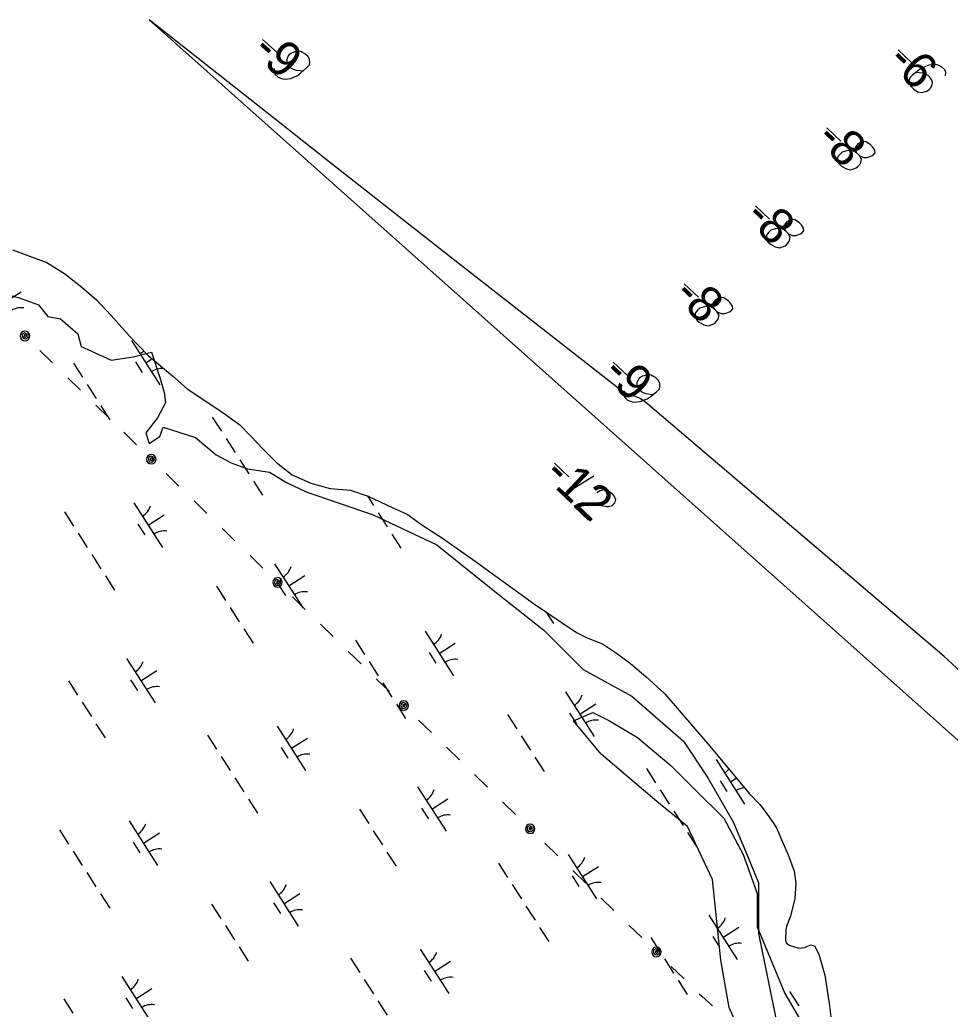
# Model space of a CAD drawing. Extents: x 3962991 to 3983549, y 181631 to 204078.
# Drawn here: x 3977393 to 3978274, y 189193 to 190129 of the extents above; entities that cross this region are included whole.
import ezdxf

# ---------------------------------------------------------------- set-up
doc = ezdxf.new("R2010")
doc.units = 0
for name, color, linetype in [('V-ANNO-MASK', 7, 'Continuous'), ('V-ANNO-MASK2', 7, 'Continuous'), ('V-RIVR-EDGE', 7, 'Continuous'), ('V-RIVR-RANG', 7, 'Continuous'), ('V-SITE-VEGE', 7, 'Continuous'), ('V-TOPO-DPTH', 7, 'Continuous'), ('V-TOPO-MINR', 7, 'Continuous'), ('V-UTIL-LINE', 7, 'Continuous'), ('V-WETL-SWMP', 7, 'Continuous')]:
    doc.layers.add(name, color=color, linetype=linetype)

msp = doc.modelspace()

# ---------------------------------------------------------------- linework, layer by layer
at = {"layer": 'V-ANNO-MASK2'}
for p, q in [((3977622.66, 190110.7), (3977636.5, 190098.47)), ((3978224.28, 190101.01), (3978237.7, 190088.33)), ((3978156.67, 190027.33), (3978170.1, 190014.65)), ((3978089.26, 189953.47), (3978102.68, 189940.79)), ((3978021.84, 189879.61), (3978035.27, 189866.93)), ((3977954.71, 189805.48), (3977968.14, 189792.8)), ((3977899.07, 189709.61), (3977912.47, 189696.9)), ((3977936.15, 189697.32), (3977906.58, 189679.2))]:
    msp.add_line(p, q, dxfattribs=at)
for points in [[(3977633.69, 190083.35), (3977633.35, 190079.78), (3977634.6, 190077.61), (3977637.37, 190075.17), (3977640.05, 190074.21), (3977641.58, 190073.56), (3977643.09, 190073.28), (3977649.4, 190074.04), (3977655.77, 190076.86), (3977658.63, 190078.9), (3977664.49, 190083.94), (3977667.11, 190086.9), (3977667.37, 190088.79), (3977667.18, 190091.76), (3977666.94, 190092.68), (3977665.49, 190095.02), (3977662.92, 190097.3), (3977660.59, 190098.65), (3977658.86, 190099.47), (3977655.49, 190099.64), (3977650.72, 190098.23), (3977648.38, 190096.77), (3977646.98, 190095.19), (3977645.7, 190091.75), (3977645.61, 190090.06), (3977646.3, 190088.05), (3977648.14, 190085.36), (3977649.92, 190083.79), (3977652.62, 190082.46), (3977654.53, 190081.83), (3977658.3, 190081.31), (3977660.36, 190081.25), (3977661.47, 190081.32)], [(3978269.02, 190076.53), (3978269.47, 190080.09), (3978268.29, 190082.3), (3978265.42, 190085.01), (3978262.77, 190086.06), (3978261.26, 190086.76), (3978259.76, 190087.09), (3978253.43, 190086.54), (3978246.97, 190083.93), (3978243.86, 190081.79), (3978237.84, 190076.95), (3978235.49, 190074.46), (3978234.81, 190072.2), (3978234.89, 190069.21), (3978235.1, 190068.29), (3978236.85, 190065.91), (3978239.15, 190063.74), (3978241.25, 190062.12), (3978242.95, 190061.23), (3978246.51, 190060.78), (3978251.33, 190062.03), (3978253.72, 190063.41), (3978255.16, 190064.94), (3978256.56, 190068.34), (3978256.7, 190070.02), (3978256.07, 190072.43), (3978254.31, 190075.18), (3978252.59, 190076.81), (3978249.93, 190078.23), (3978248.05, 190078.92), (3978244.12, 190079.37), (3978242.06, 190079.5), (3978240.94, 190079.46)], [(3978184.97, 190003.5), (3978187.65, 190000.97), (3978188.6, 190000.44), (3978191.81, 189999.22), (3978194.98, 189999.13), (3978200.34, 190000.96), (3978202.51, 190003.63), (3978202.25, 190006.05), (3978200.11, 190009.16), (3978198.19, 190010.97), (3978194, 190013.84), (3978191.38, 190014.14), (3978188.42, 190013.31), (3978186.22, 190012.12), (3978183.88, 190008.89), (3978183.56, 190007.01), (3978184.97, 190003.5), (3978181.18, 190005.64), (3978175.58, 190005.48), (3978171.33, 190004.05), (3978169.33, 190002.31), (3978166.98, 189999.45), (3978166.9, 189995.9), (3978168.48, 189992.96), (3978170.78, 189990.79), (3978175.33, 189988.3), (3978179.64, 189987.49), (3978184.63, 189989.31), (3978185.91, 189990.28), (3978188.61, 189993.53), (3978189.61, 189997.67), (3978187.65, 190000.97)], [(3978117.55, 189929.65), (3978120.24, 189927.11), (3978121.19, 189926.58), (3978124.39, 189925.36), (3978127.57, 189925.27), (3978132.93, 189927.1), (3978135.09, 189929.77), (3978134.83, 189932.19), (3978132.69, 189935.3), (3978130.78, 189937.11), (3978126.59, 189939.98), (3978123.97, 189940.28), (3978121.01, 189939.45), (3978118.8, 189938.27), (3978116.47, 189935.03), (3978116.15, 189933.15), (3978117.55, 189929.65), (3978113.76, 189931.78), (3978108.17, 189931.62), (3978103.92, 189930.19), (3978101.91, 189928.45), (3978099.57, 189925.59), (3978099.48, 189922.04), (3978101.06, 189919.1), (3978103.36, 189916.93), (3978107.91, 189914.44), (3978112.23, 189913.63), (3978117.21, 189915.46), (3978118.49, 189916.42), (3978121.2, 189919.67), (3978122.2, 189923.81), (3978120.24, 189927.11)], [(3978050.14, 189855.79), (3978052.82, 189853.25), (3978053.77, 189852.72), (3978056.98, 189851.5), (3978060.15, 189851.41), (3978065.51, 189853.24), (3978067.67, 189855.91), (3978067.42, 189858.33), (3978065.28, 189861.44), (3978063.36, 189863.25), (3978059.17, 189866.12), (3978056.55, 189866.42), (3978053.59, 189865.59), (3978051.38, 189864.41), (3978049.05, 189861.17), (3978048.73, 189859.29), (3978050.14, 189855.79), (3978046.35, 189857.92), (3978040.75, 189857.76), (3978036.5, 189856.33), (3978034.5, 189854.6), (3978032.15, 189851.73), (3978032.07, 189848.18), (3978033.64, 189845.24), (3978035.95, 189843.07), (3978040.49, 189840.58), (3978044.81, 189839.77), (3978049.8, 189841.6), (3978051.07, 189842.57), (3978053.78, 189845.81), (3978054.78, 189849.95), (3978052.82, 189853.25)], [(3977964.83, 189777.78), (3977964.38, 189774.22), (3977965.56, 189772.02), (3977968.24, 189769.48), (3977970.88, 189768.44), (3977972.4, 189767.73), (3977973.9, 189767.4), (3977980.23, 189767.96), (3977986.68, 189770.57), (3977989.61, 189772.51), (3977995.63, 189777.35), (3977998.35, 189780.23), (3977998.67, 189782.1), (3977998.59, 189785.09), (3977998.37, 189786.01), (3977997, 189788.4), (3977994.51, 189790.75), (3977992.23, 189792.18), (3977990.52, 189793.07), (3977987.16, 189793.34), (3977982.34, 189792.09), (3977979.95, 189790.71), (3977978.5, 189789.18), (3977977.11, 189785.78), (3977976.97, 189784.1), (3977977.59, 189782.06), (3977979.34, 189779.31), (3977981.07, 189777.68), (3977983.72, 189776.27), (3977985.61, 189775.57), (3977989.36, 189774.93), (3977991.42, 189774.81), (3977992.53, 189774.84)], [(3977938.98, 189681.91), (3977942.28, 189683.86), (3977945.99, 189684.71), (3977948.62, 189684.03), (3977950.89, 189682.97), (3977952.41, 189681.89), (3977953.37, 189680.98), (3977954.91, 189679.15), (3977955.69, 189677.68), (3977956.09, 189676.94), (3977956.69, 189675.28), (3977956.54, 189673.97), (3977956.19, 189672.84), (3977955.84, 189672.09), (3977955.3, 189671.14), (3977954.39, 189670.18), (3977953.3, 189669.41), (3977952.56, 189669.02), (3977951.45, 189668.61), (3977950.15, 189668.39), (3977949.03, 189668.37), (3977925.42, 189672.23), (3977921.35, 189671), (3977917.68, 189668.67), (3977931.26, 189655.78)]]:
    msp.add_lwpolyline(points, dxfattribs=at)
at = {"layer": 'V-RIVR-EDGE'}
msp.add_lwpolyline([(3977377.98, 189870.44), (3977393.27, 189866.07), (3977410.74, 189859.51), (3977419.48, 189848.59), (3977431.49, 189846.41), (3977447.88, 189832.21), (3977451.15, 189820.2), (3977460.98, 189815.83), (3977479.55, 189807.09), (3977500.3, 189810.37), (3977517.77, 189814.74), (3977525.42, 189790.71), (3977529.79, 189776.51), (3977530.88, 189766.68), (3977523.24, 189752.48), (3977512.31, 189738.29), (3977515.59, 189728.46), (3977525.42, 189735.01), (3977528.7, 189743.75), (3977559.28, 189733.92), (3977578.94, 189717.53), (3977593.13, 189709.89), (3977608.42, 189704.43), (3977629.17, 189701.15), (3977645.56, 189691.32), (3977664.12, 189682.59), (3977727.47, 189660.74), (3977787.54, 189632.35), (3977842.14, 189588.66), (3977889.11, 189551.53), (3977926.24, 189514.39), (3977972.11, 189489.27), (3978021.26, 189446.68), (3978044.19, 189411.73), (3978068.22, 189370.23), (3978082.42, 189336.37), (3978092.25, 189312.35), (3978092.25, 189264.29), (3978109.72, 189178.01)], dxfattribs=at)
at = {"layer": 'V-SITE-VEGE'}
msp.add_lwpolyline([(3978085.5, 189146.87), (3978064.43, 189194.3), (3978056.53, 189239.1), (3978048.63, 189315.52), (3978024.93, 189365.6), (3977995.95, 189389.32), (3977943.27, 189434.12), (3977916.94, 189465.74), (3977935.38, 189473.64), (3977951.18, 189465.74), (3977977.52, 189449.93), (3978009.12, 189423.57), (3978032.82, 189399.86), (3978059.16, 189373.5), (3978077.6, 189339.24), (3978090.77, 189302.35), (3978090.77, 189270.73), (3978117.11, 189207.48), (3978135.55, 189175.86)], dxfattribs=at)
at = {"layer": 'V-TOPO-DPTH'}
msp.add_lwpolyline([(3978299.23, 189497.8), (3978267.78, 189526.71), (3977985.41, 189767.28), (3977982.59, 189769.38), (3977979.62, 189771.19), (3977976.42, 189772.58), (3977973.09, 189773.69), (3977969.74, 189774.79), (3977966.51, 189776.14), (3977963.48, 189777.88), (3977960.57, 189779.87), (3977850.75, 189865.64), (3977794.76, 189909.45), (3977738.82, 189953.32), (3977682.96, 189997.29), (3977627.14, 190041.32), (3977515.59, 190129.47), (3978679.07, 189092.54)], dxfattribs=at)
at = {"layer": 'V-TOPO-MINR'}
msp.add_lwpolyline([(3978299.23, 189497.8), (3978267.78, 189526.71), (3977985.41, 189767.28), (3977982.59, 189769.38), (3977979.62, 189771.19), (3977976.42, 189772.58), (3977973.09, 189773.69), (3977969.74, 189774.79), (3977966.51, 189776.14), (3977963.48, 189777.88), (3977960.57, 189779.87), (3977850.75, 189865.64), (3977794.76, 189909.45), (3977738.82, 189953.32), (3977682.96, 189997.29), (3977627.14, 190041.32), (3977515.59, 190129.47)], dxfattribs=at)
at = {"layer": 'V-UTIL-LINE'}
for points in [[(3977397.91, 189830.12), (3977398.15, 189831.54), (3977397.1, 189831.04), (3977396.91, 189829.68), (3977398.06, 189828.78), (3977399.3, 189829.94), (3977399.33, 189832.29), (3977397.32, 189833), (3977395.22, 189831.78), (3977395.14, 189829.49), (3977396.36, 189827.62), (3977398.76, 189827.42), (3977400.8, 189829.27), (3977401.05, 189833.34), (3977399.58, 189834.3), (3977397.86, 189834.62), (3977396.14, 189834.26), (3977394.69, 189833.27), (3977393.73, 189831.79), (3977393.41, 189830.07), (3977393.78, 189828.35), (3977394.77, 189826.9), (3977396.24, 189825.94), (3977397.97, 189825.62), (3977399.68, 189825.99), (3977401.13, 189826.98), (3977402.09, 189828.45), (3977402.41, 189830.18), (3977402.05, 189831.9), (3977401.05, 189833.34)], [(3977411.92, 189816.47), (3977424.08, 189804.59)], [(3977438.4, 189790.63), (3977450.57, 189778.75)], [(3977464.88, 189764.78), (3977477.05, 189752.91)], [(3977491.36, 189738.94), (3977503.53, 189727.07)], [(3977517.43, 189713.49), (3977517.67, 189714.9), (3977516.62, 189714.41), (3977516.42, 189713.05), (3977517.58, 189712.15), (3977518.82, 189713.3), (3977518.85, 189715.65), (3977516.84, 189716.37), (3977514.74, 189715.14), (3977514.66, 189712.85), (3977515.88, 189710.98), (3977518.28, 189710.78), (3977520.32, 189712.64), (3977520.57, 189716.71), (3977519.1, 189717.66), (3977517.38, 189717.99), (3977515.66, 189717.62), (3977514.21, 189716.63), (3977513.25, 189715.16), (3977512.93, 189713.43), (3977513.29, 189711.71), (3977514.29, 189710.27), (3977515.76, 189709.31), (3977517.49, 189708.99), (3977519.2, 189709.35), (3977520.65, 189710.34), (3977521.61, 189711.81), (3977521.93, 189713.54), (3977521.57, 189715.26), (3977520.57, 189716.71)], [(3977531.44, 189699.83), (3977543.6, 189687.96)], [(3977557.92, 189673.99), (3977570.08, 189662.12)], [(3977584.4, 189648.15), (3977596.56, 189636.27)], [(3977610.88, 189622.3), (3977623.04, 189610.43)], [(3977636.95, 189596.85), (3977637.19, 189598.27), (3977636.14, 189597.77), (3977635.94, 189596.41), (3977637.1, 189595.51), (3977638.34, 189596.67), (3977638.37, 189599.01), (3977636.36, 189599.73), (3977634.26, 189598.5), (3977634.17, 189596.22), (3977635.4, 189594.35), (3977637.8, 189594.15), (3977639.84, 189596), (3977640.09, 189600.07), (3977638.62, 189601.03), (3977636.89, 189601.35), (3977635.18, 189600.99), (3977633.73, 189599.99), (3977632.77, 189598.52), (3977632.45, 189596.8), (3977632.81, 189595.08), (3977633.81, 189593.63), (3977635.28, 189592.67), (3977637, 189592.35), (3977638.72, 189592.71), (3977640.17, 189593.71), (3977641.13, 189595.18), (3977641.45, 189596.91), (3977641.09, 189598.62), (3977640.09, 189600.07)], [(3977650.96, 189583.19), (3977663.12, 189571.32)], [(3977677.44, 189557.35), (3977689.6, 189545.48)], [(3977703.92, 189531.51), (3977716.08, 189519.64)], [(3977730.4, 189505.67), (3977742.56, 189493.79)], [(3977756.47, 189480.21), (3977756.71, 189481.63), (3977755.66, 189481.13), (3977755.46, 189479.77), (3977756.62, 189478.87), (3977757.86, 189480.03), (3977757.89, 189482.38), (3977755.88, 189483.09), (3977753.78, 189481.87), (3977753.69, 189479.58), (3977754.92, 189477.71), (3977757.32, 189477.51), (3977759.36, 189479.36), (3977759.61, 189483.43), (3977758.14, 189484.39), (3977756.41, 189484.71), (3977754.7, 189484.35), (3977753.25, 189483.36), (3977752.29, 189481.88), (3977751.97, 189480.16), (3977752.33, 189478.44), (3977753.33, 189476.99), (3977754.8, 189476.04), (3977756.52, 189475.71), (3977758.24, 189476.08), (3977759.69, 189477.07), (3977760.65, 189478.54), (3977760.97, 189480.27), (3977760.61, 189481.99), (3977759.61, 189483.43)], [(3977770.47, 189466.55), (3977782.64, 189454.68)], [(3977796.95, 189440.71), (3977809.12, 189428.84)], [(3977823.43, 189414.87), (3977835.6, 189403)], [(3977849.91, 189389.03), (3977862.08, 189377.16)], [(3977875.99, 189363.58), (3977876.23, 189365), (3977875.18, 189364.5), (3977874.98, 189363.14), (3977876.14, 189362.24), (3977877.38, 189363.4), (3977877.41, 189365.74), (3977875.4, 189366.46), (3977873.3, 189365.23), (3977873.21, 189362.94), (3977874.44, 189361.07), (3977876.84, 189360.87), (3977878.88, 189362.73), (3977879.13, 189366.8), (3977877.66, 189367.76), (3977875.93, 189368.08), (3977874.22, 189367.71), (3977872.77, 189366.72), (3977871.81, 189365.25), (3977871.49, 189363.52), (3977871.85, 189361.8), (3977872.85, 189360.36), (3977874.32, 189359.4), (3977876.04, 189359.08), (3977877.76, 189359.44), (3977879.21, 189360.43), (3977880.17, 189361.91), (3977880.49, 189363.63), (3977880.13, 189365.35), (3977879.13, 189366.8)], [(3977889.99, 189349.92), (3977902.16, 189338.04)], [(3977916.47, 189324.07), (3977928.64, 189312.2)], [(3977942.95, 189298.23), (3977955.12, 189286.36)], [(3977969.43, 189272.39), (3977981.6, 189260.52)], [(3977995.51, 189246.94), (3977995.75, 189248.36), (3977994.7, 189247.86), (3977994.5, 189246.5), (3977995.66, 189245.6), (3977996.9, 189246.76), (3977996.93, 189249.1), (3977994.92, 189249.82), (3977992.82, 189248.6), (3977992.73, 189246.31), (3977993.96, 189244.44), (3977996.36, 189244.24), (3977998.39, 189246.09), (3977998.65, 189250.16), (3977997.18, 189251.12), (3977995.45, 189251.44), (3977993.74, 189251.08), (3977992.29, 189250.08), (3977991.33, 189248.61), (3977991.01, 189246.89), (3977991.37, 189245.17), (3977992.36, 189243.72), (3977993.84, 189242.76), (3977995.56, 189242.44), (3977997.28, 189242.8), (3977998.73, 189243.8), (3977999.69, 189245.27), (3978000.01, 189247), (3977999.64, 189248.71), (3977998.65, 189250.16)], [(3978009.51, 189233.28), (3978021.68, 189221.41)], [(3978035.99, 189207.44), (3978038.39, 189205.09), (3978048.49, 189195.92)]]:
    msp.add_lwpolyline(points, dxfattribs=at)
at = {"layer": 'V-WETL-SWMP'}
for p, q in [((3977379.1, 189862.32), (3977394.26, 189872.04)), ((3977498.63, 189825.83), (3977525.62, 189783.74)), ((3977512.13, 189804.78), (3977518.12, 189808.62)), ((3977443.73, 189804.53), (3977452.36, 189791.06)), ((3977502.39, 189805.67), (3977508.87, 189795.57)), ((3977456.68, 189784.33), (3977465.32, 189770.86)), ((3977469.64, 189764.12), (3977478.27, 189750.65)), ((3977575.2, 189753.4), (3977583.84, 189739.93)), ((3977588.16, 189733.2), (3977596.79, 189719.73)), ((3977601.11, 189712.99), (3977609.74, 189699.52)), ((3977614.06, 189692.79), (3977622.7, 189679.32)), ((3977721.97, 189678.73), (3977727.84, 189669.57)), ((3977501.05, 189672.1), (3977528.04, 189630.01)), ((3977435.17, 189663.63), (3977443.81, 189650.16)), ((3977514.54, 189651.06), (3977529.7, 189660.77)), ((3977732.16, 189662.83), (3977740.79, 189649.36)), ((3977504.81, 189651.94), (3977511.29, 189641.84)), ((3977448.12, 189643.42), (3977456.76, 189629.95)), ((3977745.11, 189642.63), (3977753.74, 189629.16)), ((3977461.08, 189623.22), (3977469.71, 189609.75)), ((3977634.08, 189614.56), (3977661.06, 189572.47)), ((3977474.03, 189603.02), (3977482.67, 189589.55)), ((3977647.57, 189593.52), (3977662.72, 189603.23)), ((3977579.17, 189593.26), (3977587.81, 189579.8)), ((3977637.84, 189594.4), (3977644.31, 189584.3)), ((3977592.12, 189573.06), (3977600.76, 189559.59)), ((3977891.27, 189568.59), (3977898.17, 189557.83)), ((3977605.08, 189552.86), (3977613.71, 189539.39)), ((3977776.53, 189550.61), (3977803.51, 189508.52)), ((3977710.64, 189542.14), (3977719.28, 189528.67)), ((3977790.02, 189529.56), (3977805.17, 189539.28)), ((3977780.28, 189530.45), (3977786.76, 189520.35)), ((3977494.04, 189524.79), (3977521.03, 189482.7)), ((3977723.6, 189521.93), (3977732.23, 189508.46)), ((3977507.54, 189503.74), (3977522.69, 189513.46)), ((3977439.14, 189503.49), (3977447.77, 189490.02)), ((3977497.8, 189504.63), (3977504.28, 189494.53)), ((3977736.55, 189501.73), (3977745.19, 189488.26)), ((3977909.55, 189493.07), (3977936.53, 189450.98)), ((3977452.09, 189483.29), (3977460.73, 189469.82)), ((3977749.5, 189481.52), (3977758.14, 189468.05)), ((3977923.04, 189472.02), (3977938.2, 189481.74)), ((3977854.64, 189471.77), (3977863.28, 189458.3)), ((3977913.31, 189472.91), (3977919.79, 189462.81)), ((3977465.05, 189463.08), (3977473.68, 189449.61)), ((3977636.49, 189460.84), (3977663.48, 189418.74)), ((3977570.61, 189452.36), (3977579.25, 189438.89)), ((3977867.6, 189451.57), (3977876.23, 189438.1)), ((3977649.99, 189439.79), (3977665.14, 189449.51)), ((3977583.57, 189432.16), (3977592.2, 189418.69)), ((3977640.25, 189440.68), (3977646.73, 189430.58)), ((3977880.55, 189431.36), (3977889.19, 189417.89)), ((3978052, 189429.12), (3978078.98, 189387.02)), ((3977986.12, 189420.64), (3977994.75, 189407.17)), ((3977596.52, 189411.95), (3977605.15, 189398.48)), ((3977769.52, 189403.29), (3977796.5, 189361.2)), ((3978055.76, 189408.96), (3978062.23, 189398.86)), ((3978065.49, 189408.07), (3978071.03, 189411.62)), ((3977999.07, 189400.44), (3978007.71, 189386.97)), ((3977609.47, 189391.75), (3977618.11, 189378.28)), ((3977783.01, 189382.25), (3977798.16, 189391.96)), ((3977714.61, 189382), (3977723.25, 189368.53)), ((3977773.28, 189383.14), (3977779.75, 189373.03)), ((3978012.02, 189380.23), (3978020.66, 189366.76)), ((3977496.46, 189371.06), (3977523.45, 189328.97)), ((3977430.58, 189362.59), (3977439.22, 189349.12)), ((3977509.95, 189350.02), (3977525.11, 189359.73)), ((3977727.57, 189361.79), (3977736.2, 189348.32)), ((3978024.98, 189360.03), (3978033.61, 189346.56)), ((3977500.22, 189350.9), (3977506.7, 189340.8)), ((3977443.53, 189342.38), (3977452.17, 189328.91)), ((3977740.52, 189341.59), (3977749.15, 189328.12)), ((3977911.97, 189339.34), (3977938.95, 189297.25)), ((3977846.09, 189330.87), (3977854.72, 189317.4)), ((3977456.49, 189322.18), (3977465.12, 189308.71)), ((3977915.73, 189319.18), (3977922.2, 189309.08)), ((3977925.46, 189318.3), (3977940.61, 189328.01)), ((3977629.49, 189313.52), (3977656.47, 189271.43)), ((3977859.04, 189310.67), (3977867.67, 189297.2)), ((3977469.44, 189301.98), (3977478.08, 189288.51)), ((3977642.98, 189292.48), (3977658.13, 189302.19)), ((3977574.58, 189292.22), (3977583.22, 189278.76)), ((3977633.25, 189293.36), (3977639.72, 189283.26)), ((3977871.99, 189290.46), (3977880.63, 189276.99)), ((3978044.99, 189281.8), (3978071.98, 189239.71)), ((3977587.53, 189272.02), (3977596.17, 189258.55)), ((3977884.95, 189270.26), (3977893.58, 189256.79)), ((3978058.48, 189260.76), (3978073.64, 189270.47)), ((3977990.09, 189260.51), (3977998.72, 189247.04)), ((3978048.75, 189261.64), (3978055.23, 189251.54)), ((3977600.49, 189251.82), (3977609.12, 189238.35)), ((3977771.94, 189249.57), (3977798.92, 189207.48)), ((3977706.05, 189241.1), (3977714.69, 189227.63)), ((3977785.43, 189228.52), (3977800.58, 189238.24)), ((3978003.04, 189240.3), (3978011.67, 189226.83)), ((3977775.69, 189229.41), (3977782.17, 189219.31)), ((3977489.45, 189223.75), (3977516.44, 189181.66)), ((3977719.01, 189220.89), (3977727.64, 189207.42)), ((3978015.99, 189220.1), (3978024.63, 189206.63)), ((3977502.95, 189202.7), (3977518.1, 189212.42)), ((3978121.56, 189209.38), (3978130.19, 189195.91)), ((3977434.55, 189202.45), (3977443.18, 189188.98)), ((3977493.21, 189203.59), (3977499.69, 189193.49)), ((3977731.96, 189200.69), (3977740.6, 189187.22))]:
    msp.add_line(p, q, dxfattribs=at)
for points in [[(3977386.23, 189911.56), (3977400.58, 189906.46), (3977418.54, 189899.64), (3977435.36, 189889.24), (3977451.64, 189876.45), (3977465.52, 189864.21), (3977479.45, 189849.59), (3977497.04, 189829.69), (3977514.59, 189811.57), (3977537.52, 189792.36), (3977551.4, 189780.12), (3977578.47, 189762.17), (3977588.7, 189755.22), (3977601.34, 189745.93), (3977611.63, 189735.41), (3977623.14, 189723.13), (3977635.85, 189710.28), (3977650.91, 189698.65), (3977668.29, 189690.64), (3977686.81, 189685.61), (3977705.85, 189684.16), (3977722.59, 189678.51), (3977745.37, 189667.62), (3977759.75, 189661.33), (3977773.59, 189651.47), (3977792.23, 189639.32), (3977821.73, 189618.44), (3977880.13, 189576.07)], [(3977880.13, 189576.07), (3977919.83, 189549.43), (3977930.02, 189544.26), (3977944.39, 189538.56), (3977957.62, 189529.88), (3977970.87, 189520.01), (3977985.35, 189507.78), (3978003.47, 189491.45), (3978045.95, 189441.68), (3978083.59, 189396.57), (3978093.28, 189386.63), (3978101.19, 189376.07), (3978109.12, 189364.32), (3978115.33, 189349.57), (3978120.27, 189338.96), (3978125.89, 189323.6), (3978127.29, 189311.74), (3978126.35, 189297.46), (3978122.48, 189280.75), (3978118.49, 189271.17), (3978117.95, 189268.18), (3978117.53, 189258.07), (3978118.17, 189255.71), (3978121.18, 189253.38), (3978130.14, 189250.57), (3978136.08, 189251.27), (3978141.38, 189253.74), (3978144.97, 189252.61), (3978149.26, 189244.96), (3978154.96, 189224.85), (3978159, 189198.17), (3978161.1, 189180.38)]]:
    msp.add_lwpolyline(points, dxfattribs=at)
for centre, start, end in [((3977394.21, 189839.2), 81.89186, 123.43552), ((3977497.42, 189828.16), 301.89187, 316.6647), ((3977527.23, 189781.66), 82.85376, 123.43552), ((3977499.84, 189674.44), 301.89187, 343.43553), ((3977529.65, 189627.93), 81.89186, 123.43552), ((3977632.86, 189616.9), 301.89187, 343.43553), ((3977662.68, 189570.39), 81.89186, 123.43552), ((3977775.31, 189552.95), 301.89187, 343.43553), ((3977492.83, 189527.12), 301.89187, 343.43553), ((3977805.13, 189506.44), 81.89186, 123.43552), ((3977522.64, 189480.62), 81.89186, 123.43552), ((3977908.33, 189495.4), 301.89187, 343.43553), ((3977938.15, 189448.9), 81.89186, 123.43552), ((3977635.28, 189463.17), 301.89187, 343.43553), ((3977665.09, 189416.67), 81.89186, 123.43552), ((3978050.78, 189431.45), 301.89187, 319.11129), ((3977768.3, 189405.63), 301.89187, 343.43553), ((3978080.6, 189384.95), 96.27685, 123.43552), ((3977798.12, 189359.12), 81.89186, 123.43552), ((3977495.25, 189373.4), 301.89187, 343.43553), ((3977525.06, 189326.89), 81.89186, 123.43552), ((3977910.75, 189341.68), 301.89187, 343.43553), ((3977628.27, 189315.86), 301.89187, 343.43553), ((3977940.57, 189295.17), 81.89186, 123.43552), ((3977658.09, 189269.35), 81.89186, 123.43552), ((3978043.78, 189284.14), 301.89187, 343.43553), ((3978073.59, 189237.63), 81.89186, 123.43552), ((3977770.72, 189251.91), 301.89187, 343.43553), ((3977488.24, 189226.08), 301.89187, 343.43553), ((3977800.54, 189205.4), 81.89186, 123.43552), ((3977518.05, 189179.58), 81.89186, 123.43552)]:
    msp.add_arc(centre, 17.62, start, end, dxfattribs=at)

# ---------------------------------------------------------------- texts
at = {"layer": 'V-ANNO-MASK'}
for s, rotation, p in [('-9', 318.52064, (3977611.48, 190098.06)), ('-6', 316.63192, (3978212.69, 190088.73)), ('-8', 316.63192, (3978145.08, 190015.06)), ('-8', 316.63192, (3978077.67, 189941.2)), ('-8', 316.63192, (3978010.25, 189867.34)), ('-9', 316.63192, (3977943.12, 189793.21)), ('-12', 316.48833, (3977887.45, 189697.36))]:
    msp.add_text(s, height=33.5, rotation=rotation, dxfattribs=at).set_placement(p)
at = {"layer": 'V-RIVR-RANG'}
for s, rotation, p in [('-9', 318.52064, (3977611.48, 190098.06)), ('-6', 316.63192, (3978212.69, 190088.73)), ('-8', 316.63192, (3978145.08, 190015.06)), ('-8', 316.63192, (3978077.67, 189941.2)), ('-8', 316.63192, (3978010.25, 189867.34)), ('-9', 316.63192, (3977943.12, 189793.21)), ('-12', 316.48833, (3977887.45, 189697.36))]:
    msp.add_text(s, height=33.5, rotation=rotation, dxfattribs=at).set_placement(p)

doc.saveas('drawing.dxf')
